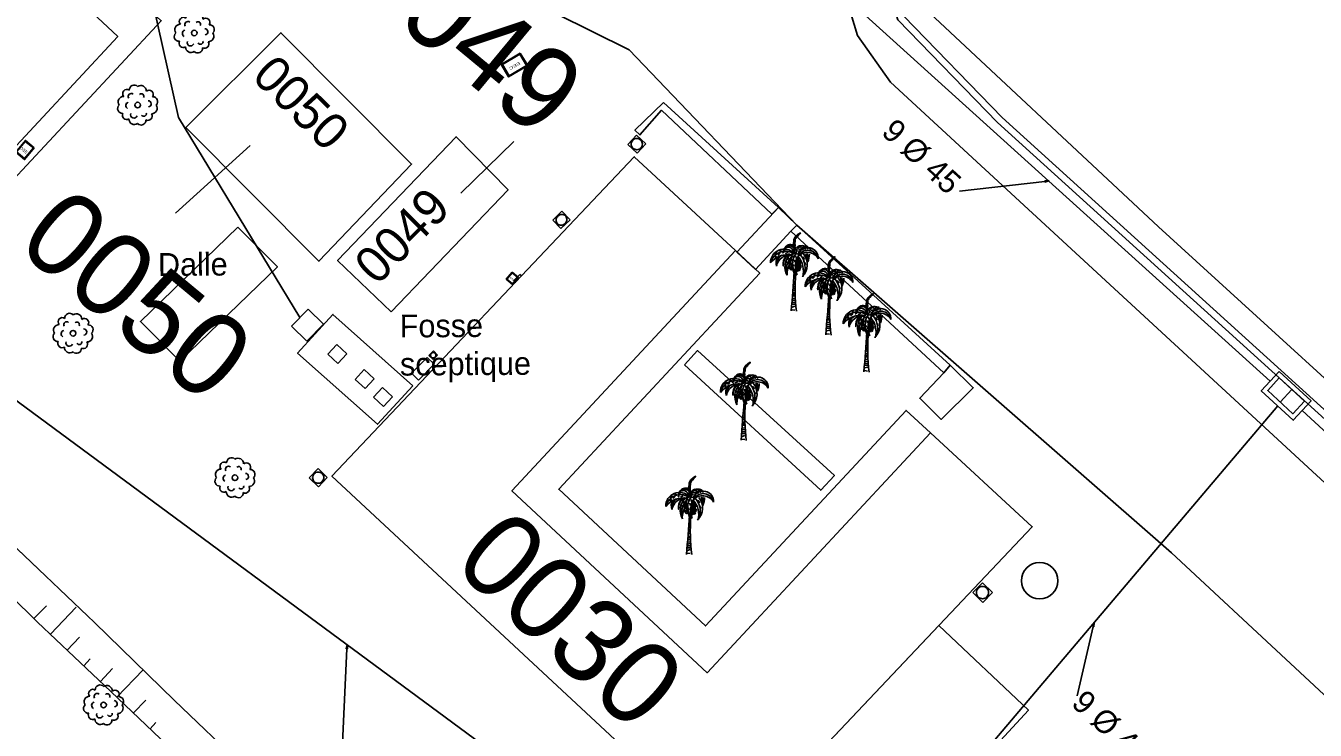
# Model space of a CAD drawing. Extents: x 343997 to 344255, y 298512 to 298767.
# Drawn here: x 344029 to 344085.4, y 298651.5 to 298682.3 of the extents above; entities that cross this region are included whole.
import ezdxf

# ---------------------------------------------------------------- set-up
doc = ezdxf.new("R2010")
doc.units = 0
for name, color, linetype in [('Default', 7, 'Continuous'), ('DH_CADRE -CARTOUCHE', 7, 'Continuous'), ('DH_CADRE-CARTOUCHE', 7, 'Continuous'), ('DH_CADRE-CARTOUCHE-NORD', 7, 'Continuous'), ('DH_TEXTE', 7, 'Continuous'), ('DIR-Projet VRD1', 7, 'Continuous'), ('EL-coffret', 7, 'Continuous'), ('GO_DALLE', 7, 'Continuous'), ('O-Projet New VRD', 7, 'Continuous'), ('PC_REBAR', 7, 'Continuous'), ('PS_MID', 7, 'Continuous'), ('PS_OBJECT', 7, 'Continuous'), ('PS_PLATE', 7, 'Continuous'), ('RES_EAU PLUVIALE', 7, 'Continuous'), ('RES_ELECTRICITE', 7, 'Continuous')]:
    doc.layers.add(name, color=color, linetype=linetype)

# ---------------------------------------------------------------- blocks, each defined once
blk = doc.blocks.new('REG_INC')
at = {"layer": 'Default'}
for p, q in [((0, 0.1), (0.1, 0.1)), ((0, 0), (0, 0.1)), ((0.1, 0.1), (0.1, 0)), ((0.1, 0), (0, 0))]:
    blk.add_line(p, q, dxfattribs=at)
for centre, start, end in [((0.05, 0.0498), 90.00577, 135.00577), ((0.05, 0.05), 45.00687, 90.00687), ((0.0498, 0.05), 135.00554, 180.00554), ((0.0501, 0.05), 180.00663, 225.00663), ((0.0499, 0.0498), 225.00686, 270.00686), ((0.0499, 0.05), 270.00577, 315.00577), ((0.0499, 0.0499), 0.00663, 45.00663), ((0.0501, 0.0499), 315.00554, 0.00554)]:
    blk.add_arc(centre, 0.044, start, end, dxfattribs=at)
blk = doc.blocks.new('R3')
at = {"layer": 'Default'}
for p, q in [((0, 0.1), (0.1, 0.1)), ((0, 0), (0, 0.1)), ((0.1, 0.1), (0.1, 0)), ((0.1, 0), (0, 0))]:
    blk.add_line(p, q, dxfattribs=at)
blk = doc.blocks.new('RES_ELECTRICITE')
at = {"layer": 'RES_ELECTRICITE'}
for points in [[(0, 0), (0, 0.1), (0.1, 0.1), (0.1, 0)], [(0.005, 0.005), (0.005, 0.095), (0.095, 0.095), (0.095, 0.005)]]:
    blk.add_lwpolyline(points, close=True, dxfattribs=at)
blk.add_text('EEC', height=0.02, dxfattribs=at).set_placement((0.0237, 0.046))
blk = doc.blocks.new('COCO')
at = {"layer": 'Default'}
for p, q in [((0.0058, 0.114), (-0.003, 0.1162)), ((-0.0026, 0.1226), (0.0061, 0.1212)), ((0.0047, 0.0655), (-0.0058, 0.0642)), ((-0.0046, 0.0891), (0.0052, 0.0927)), ((0.0054, 0.0998), (-0.0041, 0.0985)), ((-0.0037, 0.106), (0.0056, 0.1071)), ((0.0046, 0.0033), (-0.0076, 0.0051)), ((-0.0073, 0.017), (0.0045, 0.0209)), ((0.0045, 0.0292), (-0.007, 0.0288)), ((-0.0068, 0.0371), (0.0045, 0.0374)), ((0.0045, 0.047), (-0.0065, 0.0453)), ((-0.0062, 0.0537), (0.0046, 0.0552))]:
    blk.add_line(p, q, dxfattribs=at)
for points in [[(0.0029, 0.2551), (-0.0016, 0.2896), (0.0002, 0.3125), (0.0059, 0.3241), (0.0173, 0.3348), (0.0189, 0.3356), (0.0282, 0.3415), (0.0266, 0.3373), (0.02, 0.3318), (0.0143, 0.3247), (0.0093, 0.32), (0.0081, 0.3165), (0.0057, 0.3133), (0.0057, 0.3099), (0.006, 0.3037), (0.0039, 0.2989), (0.0039, 0.2944), (0.0049, 0.2877), (0.0037, 0.2841), (0.0013, 0.2736)], [(-0.0746, 0.2559), (-0.0864, 0.2483)], [(-0.077, 0.2413), (-0.0836, 0.2333)], [(-0.0607, 0.2534), (-0.0704, 0.2443)], [(-0.0636, 0.2639), (-0.0541, 0.2608)], [(-0.0421, 0.258), (-0.0503, 0.2523)], [(-0.0487, 0.268), (-0.0386, 0.265)], [(-0.0183, 0.2493), (-0.0348, 0.2417), (-0.0401, 0.2307), (-0.0448, 0.2203), (-0.0471, 0.2086), (-0.0474, 0.2023), (-0.0466, 0.1973), (-0.0455, 0.2054), (-0.0451, 0.2146), (-0.0387, 0.2292), (-0.0351, 0.2354), (-0.0284, 0.2404), (-0.0233, 0.2445), (-0.0012, 0.2495)], [(-0.0256, 0.2553), (-0.0385, 0.2508)], [(-0.0203, 0.2314), (-0.0274, 0.2258)], [(0.0015, 0.2414), (-0.0056, 0.2352)], [(0.0013, 0.2736), (0.0036, 0.2813), (0.0046, 0.2746)], [(0.0081, 0.2404), (0.0106, 0.2299)], [(0.0133, 0.2608), (0.0185, 0.2634)], [(0.0196, 0.2687), (0.0323, 0.2715)], [(0.0283, 0.2765), (0.0331, 0.2786)], [(0.0385, 0.237), (0.0469, 0.2254)], [(-0.0321, 0.1997), (-0.0364, 0.19)], [(-0.0276, 0.2151), (-0.0329, 0.2086)], [(-0.023, 0.2152), (-0.0237, 0.2043)], [(-0.0161, 0.2218), (-0.0158, 0.2122)], [(-0.0059, 0.2024), (-0.0083, 0.1998)], [(-0.004, 0.2247), (-0.0081, 0.2179)], [(-0.0025, 0.2032), (0.0002, 0.1954)], [(0.0022, 0.224), (0.0043, 0.213)], [(0.0473, 0.2115), (0.0509, 0.2012)], [(-0.0055, 0.0716), (0.0048, 0.0717), (0.0049, 0.0787), (-0.0051, 0.0795)]]:
    blk.add_lwpolyline(points, dxfattribs=at)
for centre, radius in [((-0.0187, 0.1897), 0.00384), ((-0.0144, 0.1978), 0.00616), ((-0.0124, 0.1896), 0.00376), ((-0.011, 0.184), 0.00471), ((0.0134, 0.1862), 0.00549), ((0.0208, 0.1822), 0.00626), ((0.0254, 0.1938), 0.00628)]:
    blk.add_circle(centre, radius, dxfattribs=at)
for centre, radius, start, end in [((-0.0123, 0.259), 0.0323, 122.3475, 158.7636), ((-0.0199, 0.2618), 0.0238, 4.5218, 154.101), ((-0.016, 0.2647), 0.0255, 21.0861, 122.3475), ((0.0376, 0.2508), 0.0372, 113.7681, 175.3309), ((0.0376, 0.2508), 0.0372, 113.7681, 175.3309), ((0.0418, 0.2527), 0.0326, 97.1248, 183.9512), ((0.1025, 0.2053), 0.0958, 126.6858, 153.1664), ((0.0344, 0.2407), 0.0451, 69.0817, 104.862), ((0.0493, 0.2767), 0.00679, 35.3205, 126.6858), ((-0.0427, 0.2113), 0.0595, 43.6121, 181.4625), ((-0.0291, 0.1543), 0.0918, 76.7389, 142.8025), ((-0.038, 0.1964), 0.0648, 57.9192, 166.6201), ((-0.03, 0.212), 0.0482, 151.1331, 199.5942), ((-0.0196, 0.1874), 0.0565, 78.514, 171.3504), ((-0.032, 0.2055), 0.0433, 119.0834, 188.7621), ((-0.0252, 0.2556), 0.0231, 4.2441, 134.2103), ((0.0362, 0.1922), 0.0754, 136.7113, 208.8221), ((0.0551, 0.179), 0.0879, 137.733, 194.3716), ((0.062, 0.2159), 0.0753, 153.0868, 230.1124), ((0.0659, 0.2068), 0.0718, 142.3554, 222.2794), ((-0.0007, 0.2465), 0.00563, 81.7475, 144.3035), ((-0.0189, 0.121), 0.1324, 71.3715, 81.7475), ((0.0294, 0.2595), 0.0256, 198.6765, 199.7627), ((0.0963, 0.1939), 0.09, 143.9866, 203.4288), ((0.0311, 0.2152), 0.0219, 141.856, 191.5175), ((0.0398, 0.2098), 0.0301, 136.4569, 162.0685), ((0.0357, 0.2084), 0.0244, 133.1184, 172.7534), ((-0.0404, 0.2045), 0.0619, 329.4666, 26.6793), ((0.059, 0.2015), 0.0548, 29.5654, 139.3517), ((-0.0543, 0.1744), 0.096, 344.8781, 41.1461), ((-0.0341, 0.19), 0.0828, 46.9767, 50.1231), ((0.0618, 0.2316), 0.0451, 356.1627, 159.0009), ((0.0609, 0.2187), 0.0468, 12.1077, 148.3146), ((-0.0157, 0.2027), 0.074, 51.2475, 54.5217), ((-0.0341, 0.19), 0.0828, 334.0687, 41.194), ((-0.1005, 0.1577), 0.1786, 37.5668, 40.5156), ((-0.0157, 0.2027), 0.074, 315.1472, 39.0239), ((-0.0254, 0.228), 0.0869, 28.4725, 37.0965), ((-0.1704, 0.1849), 0.2327, 7.5978, 16.3666), ((-0.0054, 0.2379), 0.0738, 25.8194, 35.3205), ((-0.0254, 0.228), 0.0869, 350.8883, 14.7063), ((-0.0482, 0.2552), 0.1161, 339.3597, 356.5925), ((0.0649, 0.1599), 0.0949, 145.5146, 182.4528), ((-8.5428, 0.7294), 8.5622, 355.11326, 356.26352), ((-0.0279, 0.1637), 0.0281, 2.1499, 36.6325), ((0.0199, 0.166), 0.0176, 166.9443, 185.5966), ((0.0544, 0.1816), 0.0474, 137.1953, 172.8987), ((0.0308, 0.2014), 0.0226, 121.4297, 182.29), ((2.7302, 0.0106), 2.7266, 175.4791, 176.5597), ((0.0372, 0.1847), 0.0277, 133.5956, 173.487), ((0.0808, 0.1542), 0.0777, 142.2358, 156.28), ((0.0242, 0.1964), 0.0147, 110.9727, 165.9756), ((0.0404, 0.1878), 0.0354, 125.0585, 146.3893), ((-0.0759, 0.1958), 0.0922, 344.8505, 15.8988), ((-0.0289, 0.211), 0.0564, 317.8279, 12.3386), ((-0.0265, 0.1505), 0.0316, 339.9997, 25.7228)]:
    blk.add_arc(centre, radius, start, end, dxfattribs=at)
blk.add_ellipse((2.7425, 0.0272), major_axis=(-2.7371, 0.0966), ratio=0.529859, start_param=6.255729, end_param=6.369141, dxfattribs=at)
blk = doc.blocks.new('ARB1')
at = {"layer": 'Default'}
blk.add_circle((0, 0), 0.0122, dxfattribs=at)
for centre, radius, start, end in [((-0.0471, 0.0503), 0.0183, 53.9554, 222.2066), ((-0.0153, 0.0664), 0.0211, 43.6925, 183.5969), ((0.0139, 0.0613), 0.0241, 358.4583, 125.1928), ((0.0501, 0.0468), 0.0183, 325.1444, 131.0175), ((-0.0613, 0.0139), 0.0241, 88.4583, 215.1928), ((-0.0373, -0.0024), 0.0149, 103.7092, 242.3465), ((-0.0276, 0.037), 0.0134, 52.4396, 209.5496), ((0.0164, 0.038), 0.0112, 330.5895, 133.7127), ((0.0458, 0.0052), 0.0137, 276.6214, 88.967), ((0.0613, -0.0139), 0.0241, 268.4583, 35.1928), ((0.0664, 0.0153), 0.0211, 313.6925, 93.5969), ((-0.0664, -0.0153), 0.0211, 133.6925, 273.5969), ((-0.0478, -0.0443), 0.019, 155.2243, 300.9377), ((-0.0163, -0.042), 0.0148, 159.5371, 338.1663), ((0.0271, -0.038), 0.0112, 210.5895, 13.7127), ((0.0448, -0.0483), 0.0188, 243.1323, 33.0297), ((-0.0139, -0.0613), 0.0241, 178.4583, 305.1928), ((0.0153, -0.0664), 0.0211, 223.6925, 3.5969)]:
    blk.add_arc(centre, radius, start, end, dxfattribs=at)

msp = doc.modelspace()

# ---------------------------------------------------------------- linework, layer by layer
at = {"layer": 'DH_CADRE -CARTOUCHE'}
msp.add_lwpolyline([(344026.391, 298688.063), (344021.173, 298682.472), (344027.812, 298676.264), (344033.029, 298681.855)], close=True, dxfattribs=at)
at = {"layer": 'DH_CADRE-CARTOUCHE'}
for points in [[(344091.665, 298656.941), (344066.817, 298679.859), (344065.379, 298681.895), (344064.833, 298683.692), (344064.865, 298685.2), (344065.154, 298686.548), (344065.609, 298687.44), (344066.641, 298688.625), (344090.832, 298714.382)], [(344032.232, 298694.322), (344032.494, 298694.078), (344035.262, 298691.929), (344038.684, 298689.77), (344042.541, 298687.653), (344055.386, 298681.278), (344062.722, 298673.608), (344079.116, 298659.278), (344094.724, 298644.749)]]:
    msp.add_lwpolyline(points, dxfattribs=at)
at = {"layer": 'DH_CADRE-CARTOUCHE-NORD'}
msp.add_line((344040.986, 298669.564), (344035.683, 298678.309), dxfattribs=at)
msp.add_lwpolyline([(344029.869, 298691.79), (344033.417, 298688.488), (344035.683, 298678.309)], dxfattribs=at)
at = {"layer": 'DH_TEXTE'}
for p, q in [((344035.556, 298674.135), (344038.817, 298677.084)), ((344050.354, 298677.272), (344048.034, 298675.013))]:
    msp.add_line(p, q, dxfattribs=at)
at = {"layer": 'DIR-Projet VRD1'}
for p, q in [((344058.942, 298688.92), (344083.424, 298666.786)), ((344023.933, 298669.374), (344062.068, 298641.235)), ((344083.757, 298665.698), (344062.821, 298641.017)), ((344084.823, 298665.5), (344103.948, 298647.853))]:
    msp.add_line(p, q, dxfattribs=at)
at = {"layer": 'EL-coffret'}
msp.add_lwpolyline([(344050.605, 298671.452), (344050.678, 298671.385), (344050.428, 298671.113), (344050.355, 298671.18)], close=True, dxfattribs=at)
at = {"layer": 'GO_DALLE'}
for points in [[(344020.546, 298681.8), (344027.856, 298674.963), (344034.929, 298682.543), (344027.611, 298689.371)], [(344056.894, 298678.972), (344055.647, 298677.763), (344055.865, 298677.55), (344056.813, 298678.629), (344061.637, 298674.087), (344061.918, 298674.376), (344056.894, 298678.972)], [(344042.396, 298662.623), (344055.614, 298676.601)], [(344061.918, 298674.376), (344062.722, 298673.608), (344062.468, 298673.339), (344060.919, 298671.674), (344060.107, 298672.429), (344061.918, 298674.376)], [(344057.812, 298667.504), (344063.774, 298662.011), (344064.365, 298662.656), (344058.376, 298668.119), (344057.812, 298667.504)], [(344069.435, 298667.48), (344070.439, 298666.494), (344069.043, 298665.113), (344068.097, 298666.035), (344069.15, 298667.15), (344069.435, 298667.48)]]:
    msp.add_lwpolyline(points, dxfattribs=at)
for points in [[(344038.281, 298673.518), (344040.014, 298671.784), (344035.75, 298667.659), (344034.017, 298669.394)], [(344062.722, 298673.608), (344062.468, 298673.339), (344069.15, 298667.15), (344069.435, 298667.48)], [(344045.931, 298666.585), (344042.441, 298669.7), (344040.893, 298668.015), (344044.383, 298664.9)], [(344059.801, 298646.434), (344058.46, 298644.956), (344062.597, 298641.269), (344072.85, 298652.396), (344068.937, 298656.096)]]:
    msp.add_lwpolyline(points, close=True, dxfattribs=at)
msp.add_circle((344073.341, 298658.058), 0.796, dxfattribs=at)
at = {"layer": 'O-Projet New VRD'}
msp.add_line((344084.377, 298666.419), (344083.869, 298665.867), dxfattribs=at)
for points in [[(344073.568, 298675.518), (344069.832, 298675.1)], [(344075.683, 298656.052), (344074.983, 298653.023)], [(344043.051, 298655.081), (344042.81, 298649.998)]]:
    msp.add_lwpolyline(points, dxfattribs=at)
for points in [[(344073.565, 298675.548), (344073.747, 298675.538), (344073.571, 298675.488)], [(344083.813, 298667.209), (344085.211, 298665.922), (344084.432, 298665.076), (344083.034, 298666.363)], [(344083.825, 298666.927), (344084.929, 298665.911), (344084.421, 298665.359), (344083.317, 298666.375)], [(344075.654, 298656.058), (344075.723, 298656.227), (344075.712, 298656.045)], [(344043.021, 298655.082), (344043.06, 298655.26), (344043.081, 298655.079)]]:
    msp.add_lwpolyline(points, close=True, dxfattribs=at)
at = {"layer": 'PC_REBAR'}
msp.add_lwpolyline([(344115.386, 298697.034), (344095.685, 298715.142), (344067.379, 298684.161), (344067.261, 298683.991), (344067.218, 298683.388), (344067.403, 298682.745), (344071.702, 298678.318), (344092.045, 298659.877), (344116.981, 298686.713), (344117.24, 298686.552), (344092.063, 298659.455), (344071.494, 298678.102), (344067.135, 298682.59), (344066.915, 298683.356), (344066.967, 298684.094), (344067.145, 298684.349), (344095.667, 298715.566), (344115.589, 298697.255)], close=True, dxfattribs=at)
msp.add_lwpolyline([(344091.233, 298661.951), (344078.543, 298673.539), (344067.651, 298683.727), (344070.267, 298686.633), (344094.013, 298711.291), (344094.723, 298711.636), (344095.462, 298711.65), (344096.516, 298711.35), (344098.055, 298710.152), (344102.625, 298705.772), (344106.459, 298702.051), (344111.683, 298696.937), (344113.434, 298695.237), (344113.122, 298693.176), (344113.133, 298690.945), (344113.53, 298689.467), (344114.335, 298687.988), (344114.712, 298687.466), (344091.233, 298661.951)], dxfattribs=at)
at = {"layer": 'PS_MID'}
for points in [[(344036.003, 298677.876), (344040.167, 298682.02), (344045.881, 298676.278), (344041.823, 298672.027)], [(344044.99, 298669.815), (344042.645, 298672.058), (344047.827, 298677.475), (344050.1, 298675.156)], [(344060.039, 298672.492), (344050.263, 298661.981), (344058.811, 298654.03), (344068.567, 298664.519), (344067.505, 298665.507), (344058.737, 298656.08), (344052.312, 298662.055), (344061.101, 298671.505)]]:
    msp.add_lwpolyline(points, close=True, dxfattribs=at)
at = {"layer": 'PS_OBJECT'}
for p, q in [((344029.364, 298656.402), (344029.908, 298656.956)), ((344030.088, 298655.712), (344031.214, 298656.904)), ((344030.815, 298655.025), (344031.35, 298655.591)), ((344031.542, 298654.338), (344031.825, 298654.637)), ((344032.27, 298653.651), (344032.805, 298654.219)), ((344032.995, 298652.963), (344034.133, 298654.153)), ((344033.718, 298652.272), (344034.259, 298652.837)), ((344034.441, 298651.581), (344034.698, 298651.849))]:
    msp.add_line(p, q, dxfattribs=at)
for points in [[(344013.309, 298674.045), (344016.677, 298670.884), (344019.994, 298667.792), (344024.403, 298663.589), (344028.025, 298660.019), (344032.009, 298656.228), (344035.513, 298652.822), (344038.498, 298649.953), (344041.923, 298646.692), (344044.756, 298643.58), (344054.456, 298635.377)], [(344054.456, 298635.377), (344052.269, 298635.996), (344049.579, 298637.638), (344045.345, 298641.507), (344040.154, 298646.415), (344036.423, 298649.686), (344032.732, 298653.214), (344029.519, 298656.25), (344025.888, 298659.813), (344022.228, 298663.281), (344018.635, 298666.633), (344015.082, 298669.913), (344012.021, 298672.665)]]:
    msp.add_lwpolyline(points, dxfattribs=at)
at = {"layer": 'PS_PLATE'}
msp.add_lwpolyline([(344050.263, 298661.981), (344060.039, 298672.492), (344055.614, 298676.601), (344042.396, 298662.623), (344059.801, 298646.434), (344073.019, 298660.413), (344068.567, 298664.519), (344058.811, 298654.03)], close=True, dxfattribs=at)

# ---------------------------------------------------------------- block references
at = {"layer": 'DH_CADRE-CARTOUCHE-NORD'}
for p, xscale, yscale, rotation in [((344040.622, 298669.191), 9.43007030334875, 10.415593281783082, -44.256330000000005), ((344042.647, 298667.554), 5.983250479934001, -5.81180472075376, 137.17467), ((344046.186, 298666.833), 4.26059376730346, -9.637698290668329, 135.78777000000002), ((344043.846, 298666.456), 5.983250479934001, -5.81180472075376, 137.17467), ((344044.653, 298665.674), 5.983250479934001, -5.81180472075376, 137.17467)]:
    msp.add_blockref('R3', p, dxfattribs=dict(at, xscale=xscale, yscale=yscale, rotation=rotation))
at = {"layer": 'PC_REBAR', "xscale": 10, "yscale": 10}
for name, p in [('ARB1', (344036.374, 298682.011)), ('ARB1', (344033.898, 298678.86)), ('COCO', (344062.597, 298669.854)), ('COCO', (344064.109, 298668.81)), ('COCO', (344065.774, 298667.192)), ('ARB1', (344031.074, 298668.878)), ('COCO', (344060.403, 298664.197)), ('ARB1', (344038.154, 298662.56)), ('COCO', (344058.017, 298659.209)), ('ARB1', (344032.408, 298652.622))]:
    msp.add_blockref(name, p, dxfattribs=at)
at = {"layer": 'RES_EAU PLUVIALE'}
for p, xscale, yscale, rotation in [((344055.719, 298677.546), 5.59179728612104, 5.561469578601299, -133.59555000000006), ((344052.052, 298673.828), 5.594354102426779, -5.1482037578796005, 43.87266), ((344046.829, 298668.108), 2.60334223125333, -2.77753138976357, -44.12016625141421), ((344041.787, 298662.958), 5.59179728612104, 5.561469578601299, -133.59555000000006), ((344070.852, 298657.107), 6.044024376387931, 6.128218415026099, 45.55520999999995)]:
    msp.add_blockref('REG_INC', p, dxfattribs=dict(at, xscale=xscale, yscale=yscale, rotation=rotation))
at = {"layer": 'RES_ELECTRICITE'}
for p, xscale, yscale, rotation in [((344050.63, 298681.131), 9.75083042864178, 6.30212535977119, -148.96566), ((344029.377, 298676.991), 5.039776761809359, 6.650433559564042, 140.49315), ((344050.271, 298671.551), 3.6507635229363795, -3.9515737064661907, -40.03803000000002)]:
    msp.add_blockref('RES_ELECTRICITE', p, dxfattribs=dict(at, xscale=xscale, yscale=yscale, rotation=rotation))

# ---------------------------------------------------------------- texts
at = {"layer": 'DH_TEXTE'}
for s, height, rotation, p in [('0049', 3.662, 320.3665, (344042.992, 298684.271)), ('0050', 1.5764, 315.4316, (344038.833, 298680.051)), ('0050', 3.662, 320.3665, (344028.513, 298672.644)), ('0049', 1.5764, 45.4316, (344044.366, 298670.928)), ('Dalle', 1.0003, 0.3665, (344034.789, 298671.385)), ('Fosse', 1.0003, 0.3665, (344045.362, 298668.694)), ('sceptique', 1.0003, 0.3665, (344045.373, 298667.027)), ('0030', 3.662, 317.2565, (344047.604, 298658.724))]:
    msp.add_text(s, height=height, rotation=rotation, dxfattribs=at).set_placement(p)
at = {"layer": 'O-Projet New VRD'}
for p in [(344066.375, 298677.609), (344074.681, 298652.627)]:
    msp.add_text('9 Ø 45', height=1.0003, rotation=317.3672, dxfattribs=at).set_placement(p)

doc.saveas('drawing.dxf')
